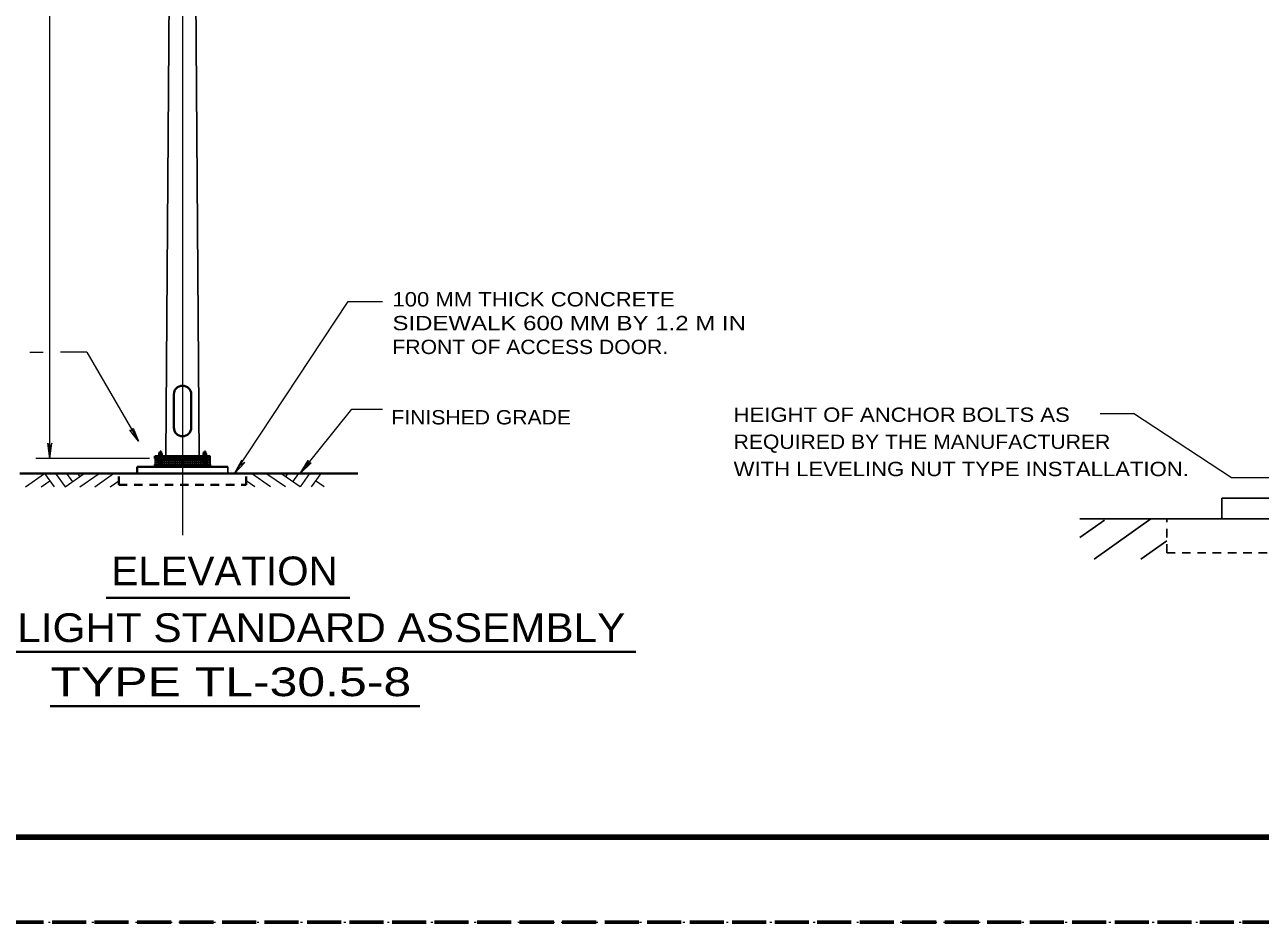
# Model space of a CAD drawing. Extents: x 312583 to 312854, y 144419 to 144597.
# Drawn here: x 312628 to 312693.4, y 144418.6 to 144466.1 of the extents above; entities that cross this region are included whole.
import ezdxf
from ezdxf.enums import TextEntityAlignment as Align

# ---------------------------------------------------------------- set-up
doc = ezdxf.new("R2010")
doc.units = 0
doc.header["$LTSCALE"] = 0.3
for name, pattern in [('DOTTED', [1.5, 0.3, -1.2]), ('LONG_DASHED', [7.5, 6, -1.5]), ('SHORT_DASHED', [2.7, 1.5, -1.2])]:
    doc.linetypes.add(name, pattern=pattern)
for name, color, linetype, lineweight in [('1', 7, 'Continuous', 13), ('2', 7, 'Continuous', 13), ('61', 7, 'LONG_DASHED', 60), ('63', 7, 'DOTTED', 13)]:
    doc.layers.add(name, color=color, linetype=linetype, lineweight=lineweight)

msp = doc.modelspace()

# ---------------------------------------------------------------- linework, layer by layer
at = {"layer": '1'}
for p, q in [((312636.3575, 144539.0263), (312636.3575, 144439.0913)), ((312634.8931, 144443.1469), (312634.8931, 144442.8249)), ((312634.8931, 144443.1086), (312637.8218, 144443.1086)), ((312634.8931, 144443.0319), (312637.8218, 144443.0319)), ((312634.9928, 144443.1469), (312634.9928, 144442.8249)), ((312635.0924, 144443.1469), (312635.0924, 144442.8249)), ((312635.1921, 144443.1469), (312635.1921, 144442.8249)), ((312635.2918, 144443.1469), (312635.2918, 144442.8249)), ((312635.3914, 144443.1469), (312635.3914, 144442.8249)), ((312635.4911, 144443.1469), (312635.4911, 144442.8249)), ((312635.5908, 144443.1469), (312635.5908, 144442.8249)), ((312635.6904, 144443.1469), (312635.6904, 144442.8249)), ((312635.7901, 144443.1469), (312635.7901, 144442.8249)), ((312635.8898, 144443.1469), (312635.8898, 144442.8249)), ((312635.9894, 144443.1469), (312635.9894, 144442.8249)), ((312636.0891, 144443.1469), (312636.0891, 144442.8249)), ((312636.1888, 144443.1469), (312636.1888, 144442.8249)), ((312636.2884, 144443.1469), (312636.2884, 144442.8249)), ((312636.3881, 144443.1469), (312636.3881, 144442.8249)), ((312636.4878, 144443.1469), (312636.4878, 144442.8249)), ((312636.5874, 144443.1469), (312636.5874, 144442.8249)), ((312636.6871, 144443.1469), (312636.6871, 144442.8249)), ((312636.7868, 144443.1469), (312636.7868, 144442.8249)), ((312636.8864, 144443.1469), (312636.8864, 144442.8249)), ((312636.9861, 144443.1469), (312636.9861, 144442.8249)), ((312637.0858, 144443.1469), (312637.0858, 144442.8249)), ((312637.1854, 144443.1469), (312637.1854, 144442.8249)), ((312637.2851, 144443.1469), (312637.2851, 144442.8249)), ((312637.3848, 144443.1469), (312637.3848, 144442.8249)), ((312637.4844, 144443.1469), (312637.4844, 144442.8249)), ((312637.5841, 144443.1469), (312637.5841, 144442.8249)), ((312637.6838, 144443.1469), (312637.6838, 144442.8249)), ((312637.7834, 144443.1469), (312637.7834, 144442.8249)), ((312637.8218, 144443.1469), (312637.8218, 144442.8249)), ((312634.8931, 144442.9476), (312637.8218, 144442.9476)), ((312634.8931, 144442.8709), (312637.8218, 144442.8709))]:
    msp.add_line(p, q, dxfattribs=at)
at = {"layer": '1', "lineweight": 40}
for p, q in [((312645.6341, 144442.3419), (312627.7478, 144442.3419)), ((312633.9578, 144442.7099), (312633.9578, 144442.3419)), ((312638.7494, 144442.7099), (312633.9578, 144442.7099))]:
    msp.add_line(p, q, dxfattribs=at)
at = {"layer": '1', "linetype": 'SHORT_DASHED', "lineweight": 40}
msp.add_line((312632.9841, 144441.7439), (312632.9841, 144442.3419), dxfattribs=at)
at = {"layer": '1', "lineweight": 25}
for p, q in [((312638.7494, 144442.7099), (312638.7494, 144442.3419)), ((312691.3691, 144441.041), (312691.3691, 144439.9447)), ((312705.7518, 144441.041), (312691.3691, 144441.041)), ((312713.2344, 144439.9447), (312683.8558, 144439.9447))]:
    msp.add_line(p, q, dxfattribs=at)
at = {"layer": '1', "linetype": 'SHORT_DASHED', "lineweight": 25}
msp.add_line((312688.4481, 144438.1584), (312688.4481, 144439.9447), dxfattribs=at)
at = {"layer": '1', "lineweight": 158}
msp.add_line((312616.5, 144423.0846), (312849, 144423.0846), dxfattribs=at)
at = {"layer": '1', "linetype": 'SHORT_DASHED', "lineweight": 40}
msp.add_lwpolyline([(312632.9841, 144441.7439), (312639.7308, 144441.7439), (312639.7308, 144442.3419)], dxfattribs=at)
at = {"layer": '1', "linetype": 'SHORT_DASHED', "lineweight": 25}
msp.add_lwpolyline([(312688.4481, 144438.1584), (312708.6958, 144438.1584), (312708.6958, 144439.9447)], dxfattribs=at)
at = {"layer": '2'}
for p, q in [((312629.3348, 144443.1469), (312629.3348, 144538.9802)), ((312628.2748, 144448.7742), (312628.9821, 144448.7742)), ((312631.2898, 144448.7742), (312629.8944, 144448.7742)), ((312631.2898, 144448.7742), (312634.0268, 144444.0669)), ((312642.5828, 144442.3419), (312645.3198, 144445.7612)), ((312645.3198, 144445.7612), (312646.9374, 144445.7612)), ((312684.9269, 144445.5337), (312686.6848, 144445.5337)), ((312629.2351, 144443.9596), (312629.3348, 144443.6989)), ((312629.3348, 144443.1469), (312629.2351, 144443.9596)), ((312629.2351, 144443.9596), (312629.3348, 144443.6989)), ((312629.3348, 144443.1469), (312629.2351, 144443.9596)), ((312629.4344, 144443.9596), (312629.3348, 144443.6989)), ((312629.3348, 144443.1469), (312629.4344, 144443.9596)), ((312629.4344, 144443.9596), (312629.3348, 144443.6989)), ((312629.3348, 144443.1469), (312629.4344, 144443.9596)), ((312634.6094, 144443.1469), (312628.5988, 144443.1469)), ((312635.0848, 144443.3386), (312635.0848, 144443.2696)), ((312635.0848, 144443.0779), (312635.0848, 144443.1469)), ((312635.0848, 144442.9936), (312635.0848, 144443.0702)), ((312635.1154, 144443.4842), (312635.1231, 144443.4996)), ((312635.1154, 144443.4766), (312635.2534, 144443.4766)), ((312635.1154, 144443.4689), (312635.2534, 144443.4689)), ((312635.1154, 144443.4536), (312635.2534, 144443.4536)), ((312635.1154, 144443.4459), (312635.2534, 144443.4459)), ((312635.1154, 144443.4382), (312635.2534, 144443.4382)), ((312635.1154, 144443.4229), (312635.2534, 144443.4229)), ((312635.2534, 144442.9859), (312635.1154, 144442.9859)), ((312635.1154, 144442.9859), (312635.1154, 144442.8249)), ((312635.2534, 144442.9782), (312635.1154, 144442.9782)), ((312635.2534, 144442.9706), (312635.1154, 144442.9706)), ((312635.1231, 144443.4996), (312635.2458, 144443.4996)), ((312635.1461, 144443.4152), (312635.1461, 144443.3462)), ((312635.1461, 144443.3386), (312635.1461, 144443.2696)), ((312635.1461, 144443.0779), (312635.1461, 144443.1469)), ((312635.1461, 144442.9936), (312635.1461, 144443.0702)), ((312635.1844, 144443.5762), (312635.1844, 144443.2466)), ((312635.1844, 144443.1852), (312635.1844, 144443.2236)), ((312635.1844, 144443.1699), (312635.1844, 144442.8249)), ((312635.2228, 144443.4152), (312635.2228, 144443.3462)), ((312635.2228, 144443.3386), (312635.2228, 144443.2696)), ((312635.2228, 144443.0779), (312635.2228, 144443.1469)), ((312635.2228, 144442.9936), (312635.2228, 144443.0702)), ((312635.2458, 144443.4996), (312635.2534, 144443.4842)), ((312635.2534, 144443.4229), (312635.2534, 144443.4842)), ((312635.2534, 144442.9859), (312635.2534, 144442.8249)), ((312635.2841, 144443.4152), (312635.2841, 144443.3462)), ((312635.2841, 144443.3386), (312635.2841, 144443.2696)), ((312635.2841, 144443.0779), (312635.2841, 144443.1469)), ((312637.4308, 144443.3386), (312637.4308, 144443.2696)), ((312637.4308, 144443.0779), (312637.4308, 144443.1469)), ((312637.4308, 144442.9936), (312637.4308, 144443.0702)), ((312637.4614, 144443.4842), (312637.4691, 144443.4996)), ((312637.4614, 144443.4766), (312637.5994, 144443.4766)), ((312637.4614, 144443.4689), (312637.5994, 144443.4689)), ((312637.4614, 144443.4536), (312637.5994, 144443.4536)), ((312637.4614, 144443.4459), (312637.5994, 144443.4459)), ((312637.4614, 144443.4382), (312637.5994, 144443.4382)), ((312637.4614, 144443.4229), (312637.5994, 144443.4229)), ((312637.5994, 144442.9859), (312637.4614, 144442.9859)), ((312637.4614, 144442.9859), (312637.4614, 144442.8249)), ((312637.5994, 144442.9782), (312637.4614, 144442.9782)), ((312637.5994, 144442.9706), (312637.4614, 144442.9706)), ((312637.4691, 144443.4996), (312637.5841, 144443.4996)), ((312637.4844, 144443.4152), (312637.4844, 144443.3462)), ((312637.4844, 144443.3386), (312637.4844, 144443.2696)), ((312637.4844, 144443.0779), (312637.4844, 144443.1469)), ((312637.4844, 144442.9936), (312637.4844, 144443.0702)), ((312637.5304, 144443.5762), (312637.5304, 144443.2466)), ((312637.5304, 144443.1852), (312637.5304, 144443.2236)), ((312637.5304, 144443.1699), (312637.5304, 144442.8249)), ((312637.5688, 144443.4152), (312637.5688, 144443.3462)), ((312637.5688, 144443.3386), (312637.5688, 144443.2696)), ((312637.5688, 144443.0779), (312637.5688, 144443.1469)), ((312637.5688, 144442.9936), (312637.5688, 144443.0702)), ((312637.5841, 144443.4996), (312637.5994, 144443.4842)), ((312637.5994, 144443.4229), (312637.5994, 144443.4842)), ((312637.5994, 144442.9859), (312637.5994, 144442.8249)), ((312637.6301, 144443.4152), (312637.6301, 144443.3462)), ((312637.6301, 144443.3386), (312637.6301, 144443.2696)), ((312637.6301, 144443.0779), (312637.6301, 144443.1469)), ((312639.1021, 144442.3419), (312639.4931, 144443.0549)), ((312639.4931, 144443.0549), (312639.4241, 144442.7942)), ((312642.5828, 144442.3419), (312643.0121, 144443.0396)), ((312643.0121, 144443.0396), (312642.9278, 144442.7712)), ((312628.0468, 144441.6366), (312629.0511, 144442.3419)), ((312629.0511, 144442.3419), (312629.5571, 144441.6366)), ((312629.6414, 144442.3419), (312630.1398, 144441.6366)), ((312630.1398, 144441.6366), (312631.1594, 144442.3496)), ((312630.2164, 144442.3419), (312630.5308, 144441.9049)), ((312630.8068, 144442.3419), (312630.9218, 144442.1809)), ((312630.9218, 144441.6366), (312631.8878, 144442.3189)), ((312631.7114, 144441.6366), (312632.7081, 144442.3419)), ((312635.2534, 144442.9552), (312635.1154, 144442.9552)), ((312635.2534, 144442.9476), (312635.1154, 144442.9476)), ((312635.2534, 144442.9399), (312635.1154, 144442.9399)), ((312635.2534, 144442.9246), (312635.1154, 144442.9246)), ((312635.2534, 144442.9169), (312635.1154, 144442.9169)), ((312637.5994, 144442.9552), (312637.4614, 144442.9552)), ((312637.5994, 144442.9476), (312637.4614, 144442.9476)), ((312637.5994, 144442.9399), (312637.4614, 144442.9399)), ((312637.5994, 144442.9246), (312637.4614, 144442.9246)), ((312637.5994, 144442.9169), (312637.4614, 144442.9169)), ((312639.1021, 144442.3419), (312639.6541, 144442.9399)), ((312639.6541, 144442.9399), (312639.4241, 144442.7942)), ((312641.0111, 144441.6366), (312640.0144, 144442.3419)), ((312641.8008, 144441.6366), (312640.8271, 144442.3189)), ((312642.5751, 144441.6366), (312641.5631, 144442.3496)), ((312641.9158, 144442.3419), (312641.8008, 144442.1809)), ((312642.4984, 144442.3419), (312642.1841, 144441.9049)), ((312643.0811, 144442.3419), (312642.5751, 144441.6366)), ((312642.5828, 144442.3419), (312643.1731, 144442.9092)), ((312643.1731, 144442.9092), (312642.9278, 144442.7712)), ((312643.6714, 144442.3419), (312643.1578, 144441.6366)), ((312628.8748, 144441.6366), (312629.3271, 144441.9586)), ((312632.5241, 144441.6366), (312632.9841, 144441.9586)), ((312640.1908, 144441.6366), (312639.7308, 144441.9586)), ((312643.8478, 144441.6366), (312643.3878, 144441.9586))]:
    msp.add_line(p, q, dxfattribs=at)
at = {"layer": '2', "lineweight": 25}
for p, q in [((312636.1734, 144538.9802), (312635.4758, 144443.2696)), ((312636.5414, 144538.9802), (312637.2314, 144443.2696)), ((312637.8218, 144443.2696), (312637.8218, 144443.1469)), ((312634.8931, 144442.7099), (312637.8218, 144442.7099)), ((312683.8558, 144438.9557), (312685.1591, 144439.8757)), ((312684.6148, 144437.8134), (312687.6048, 144439.9447)), ((312687.0681, 144437.8134), (312688.4481, 144438.7794))]:
    msp.add_line(p, q, dxfattribs=at)
at = {"layer": '2', "lineweight": 40}
for p, q in [((312635.8974, 144446.5432), (312635.8974, 144444.7876)), ((312636.8174, 144446.5432), (312636.8174, 144444.7876)), ((312634.8931, 144443.2696), (312634.8931, 144443.1469)), ((312634.8931, 144443.2696), (312637.8218, 144443.2696)), ((312634.8931, 144443.1469), (312637.8218, 144443.1469)), ((312634.8931, 144442.8249), (312637.8218, 144442.8249)), ((312634.8931, 144442.8249), (312634.8931, 144442.7099)), ((312637.8218, 144442.8249), (312637.8218, 144442.7099)), ((312632.3179, 144435.7588), (312645.2096, 144435.7588)), ((312618.7257, 144432.8992), (312660.3432, 144432.8992)), ((312629.3573, 144430.0318), (312648.9168, 144430.0318))]:
    msp.add_line(p, q, dxfattribs=at)
at = {"layer": '2'}
for points in [[(312639.1021, 144442.3419), (312645.1204, 144451.4652), (312646.9374, 144451.4652)], [(312694.7271, 144442.1144), (312691.8828, 144442.1144), (312686.6848, 144445.5337)], [(312635.0848, 144443.4152), (312635.0848, 144443.3462), (312635.2841, 144443.3462)], [(312635.2841, 144442.9936), (312635.2841, 144443.0702), (312635.0848, 144443.0702)], [(312635.1154, 144443.4229), (312635.1154, 144443.4842), (312635.2534, 144443.4842)], [(312637.4308, 144443.4152), (312637.4308, 144443.3462), (312637.6301, 144443.3462)], [(312637.6301, 144442.9936), (312637.6301, 144443.0702), (312637.4308, 144443.0702)], [(312637.4614, 144443.4229), (312637.4614, 144443.4842), (312637.5994, 144443.4842)]]:
    msp.add_lwpolyline(points, dxfattribs=at)
msp.add_lwpolyline([(312633.7431, 144444.7492), (312634.0268, 144444.0669), (312633.5744, 144444.6496), (312633.6971, 144444.6419)], close=True, dxfattribs=at)
at = {"layer": '2', "lineweight": 40}
for centre, start, end in [((312636.3558, 144446.5414), 0, 180), ((312636.3558, 144444.7845), 180, 0)]:
    msp.add_arc(centre, 0.4592, start, end, dxfattribs=at)
at = {"layer": '2'}
for centre, radius, start, end in [((312635.1144, 144443.3763), 0.0499, 53.1301, 126.8699), ((312635.1144, 144443.2964), 0.0499, 53.1301, 126.8699), ((312635.1144, 144443.1167), 0.0499, 233.1301, 306.8699), ((312635.1144, 144443.0369), 0.0499, 233.1301, 306.8699), ((312635.1843, 144443.3413), 0.0848, 61.92751, 118.07249), ((312635.1843, 144443.2615), 0.0848, 61.92751, 118.07249), ((312635.1843, 144443.1517), 0.0848, 241.92751, 298.07249), ((312635.1843, 144443.0718), 0.0848, 241.92751, 298.07249), ((312635.2542, 144443.3763), 0.0499, 53.1301, 126.8699), ((312635.2542, 144443.2964), 0.0499, 53.1301, 126.8699), ((312635.2542, 144443.1167), 0.0499, 233.1301, 306.8699), ((312635.2542, 144443.0369), 0.0499, 233.1301, 306.8699), ((312637.4577, 144443.3763), 0.0499, 53.1301, 126.8699), ((312637.4577, 144443.2964), 0.0499, 53.1301, 126.8699), ((312637.4577, 144443.1167), 0.0499, 233.1301, 306.8699), ((312637.4577, 144443.0369), 0.0499, 233.1301, 306.8699), ((312637.5276, 144443.3413), 0.0848, 61.92751, 118.07249), ((312637.5276, 144443.2615), 0.0848, 61.92751, 118.07249), ((312637.5276, 144443.1517), 0.0848, 241.92751, 298.07249), ((312637.5276, 144443.0718), 0.0848, 241.92751, 298.07249), ((312637.5974, 144443.3763), 0.0499, 53.1301, 126.8699), ((312637.5974, 144443.2964), 0.0499, 53.1301, 126.8699), ((312637.5974, 144443.1167), 0.0499, 233.1301, 306.8699), ((312637.5974, 144443.0369), 0.0499, 233.1301, 306.8699)]:
    msp.add_arc(centre, radius, start, end, dxfattribs=at)
at = {"layer": '61'}
msp.add_line((312851.75, 144418.5846), (312583.526, 144418.5846), dxfattribs=at)
at = {"layer": '63'}
msp.add_lwpolyline([(312601.2, 144418.5846), (312853.5, 144418.5846), (312853.5, 144596.7846)], dxfattribs=at)

# ---------------------------------------------------------------- texts
at = {"layer": '2'}
for s, width, p in [('100 MM THICK CONCRETE', 1.15, (312647.4664, 144451.1959)), ('SIDEWALK 600 MM BY 1.2 M IN', 1.25, (312647.4664, 144449.9359)), ('FRONT OF ACCESS DOOR.', 1.1, (312647.4664, 144448.6759)), ('FINISHED GRADE', 1.1, (312647.4128, 144444.9481)), ('HEIGHT OF ANCHOR BOLTS AS', 1.15, (312665.5245, 144445.0854)), ('REQUIRED BY THE MANUFACTURER', 1.1, (312665.5245, 144443.6517)), ('WITH LEVELING NUT TYPE INSTALLATION.', 1.15, (312665.5245, 144442.2104))]:
    msp.add_text(s, height=0.76, dxfattribs=dict(at, width=width)).set_placement(p)
for s, width, p in [('ELEVATION', 1.05, (312638.58, 144436.4342)), ('TOWER LIGHT STANDARD ASSEMBLY', 1.1, (312639.2306, 144433.4267)), ('TYPE TL-30.5-8', 1.3, (312638.9126, 144430.5593))]:
    msp.add_text(s, height=1.52, dxfattribs=dict(at, width=width)).set_placement(p, align=Align.CENTER)

doc.saveas('drawing.dxf')
